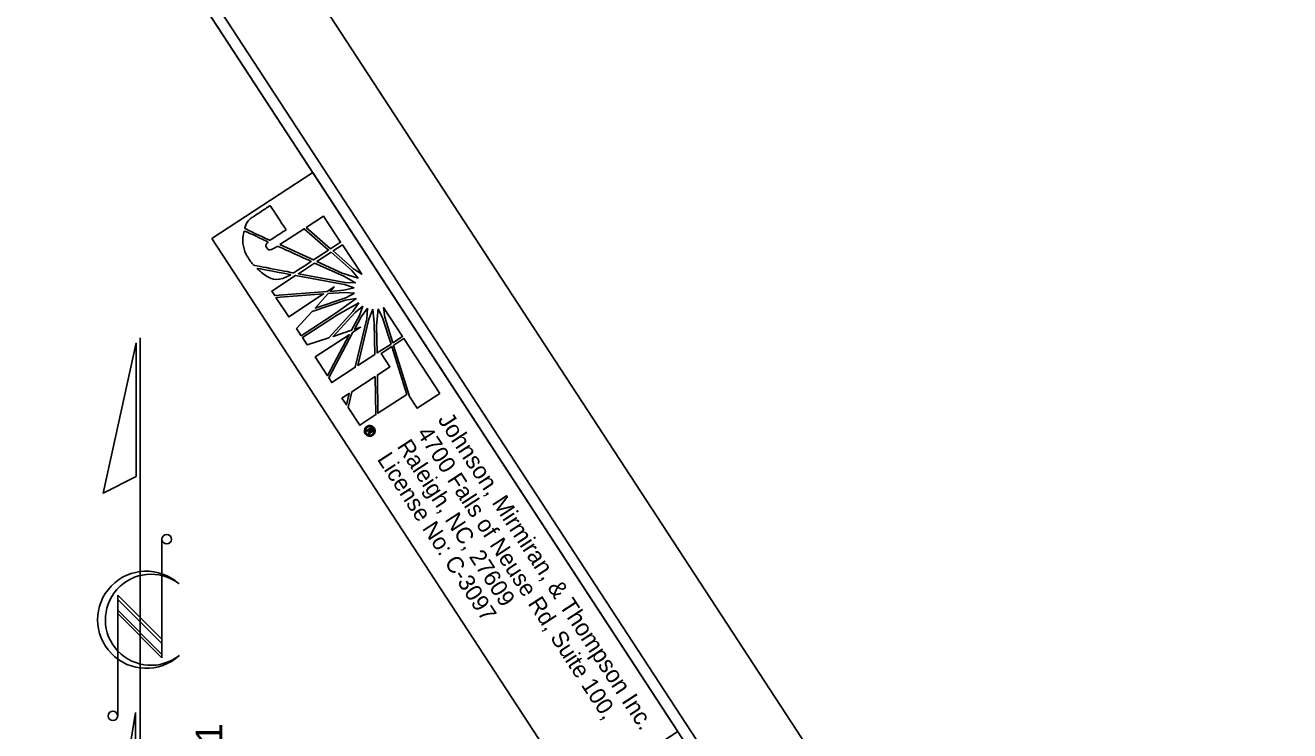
# Model space of a CAD drawing. Extents: x 1639622 to 2864602, y 842655 to 973236.
# Drawn here: x 1641174.9 to 1641458.9, y 843422.9 to 843581.5 of the extents above; entities that cross this region are included whole.
import ezdxf

# ---------------------------------------------------------------- set-up
doc = ezdxf.new("R2010")
doc.units = 0
for name, color, linetype in [('Prop Dimension Text', 7, 'Continuous'), ('Sheet North Arrow CELL', 7, 'Continuous'), ('Sheet Plan CELL', 7, 'Continuous'), ('Sheet Plot Border Inside CELL', 7, 'Continuous'), ('Sheet Plot Border Outside CELL', 7, 'Continuous')]:
    doc.layers.add(name, color=color, linetype=linetype)

msp = doc.modelspace()

# ---------------------------------------------------------------- linework, layer by layer
at = {"layer": 'Prop Dimension Text'}
for p, q in [((1641241.83, 843538.56), (1641237.94, 843536.01)), ((1641245.68, 843532.68), (1641241.83, 843538.56)), ((1641237.49, 843535.72), (1641232.01, 843532.14)), ((1641242.98, 843530.92), (1641237.49, 843535.72)), ((1641237.94, 843536.01), (1641243.41, 843531.2)), ((1641232.01, 843532.14), (1641239.58, 843528.69)), ((1641243.41, 843531.2), (1641245.68, 843532.68)), ((1641246.11, 843532.09), (1641244, 843530.71)), ((1641250.43, 843525.48), (1641246.11, 843532.09)), ((1641239.58, 843528.69), (1641242.98, 843530.92)), ((1641243.55, 843530.42), (1641240.37, 843528.34)), ((1641248.12, 843526.38), (1641243.55, 843530.42)), ((1641244, 843530.71), (1641248.58, 843526.68)), ((1641239.85, 843528), (1641236.19, 843525.6)), ((1641246.42, 843525.03), (1641239.85, 843528)), ((1641240.37, 843528.34), (1641246.04, 843525.75)), ((1641248.58, 843526.68), (1641250.43, 843525.48)), ((1641235.57, 843525.2), (1641230.23, 843521.71)), ((1641246.53, 843523.16), (1641235.57, 843525.2)), ((1641236.19, 843525.6), (1641246.69, 843523.62)), ((1641246.04, 843525.75), (1641249.61, 843524.61)), ((1641249.02, 843523.53), (1641246.42, 843525.03)), ((1641246.69, 843523.62), (1641249.02, 843523.53)), ((1641249.61, 843524.61), (1641248.12, 843526.38)), ((1641230.23, 843521.71), (1641230.87, 843520.74)), ((1641230.87, 843520.74), (1641242.68, 843521.62)), ((1641241.84, 843521.06), (1641231.16, 843520.29)), ((1641234.03, 843515.9), (1641241.84, 843521.06)), ((1641242.91, 843521.12), (1641240, 843517.87)), ((1641242.68, 843521.62), (1641244.24, 843522.63)), ((1641246.53, 843521.39), (1641242.91, 843521.12)), ((1641244.24, 843522.63), (1641243.36, 843521.64)), ((1641243.36, 843521.64), (1641246.4, 843521.88)), ((1641246.4, 843521.88), (1641248.75, 843522.39)), ((1641248.75, 843522.39), (1641246.53, 843523.16)), ((1641248.78, 843521.2), (1641246.53, 843521.39)), ((1641246.86, 843520.18), (1641248.78, 843521.2)), ((1641231.16, 843520.29), (1641234.03, 843515.9)), ((1641246.75, 843519.64), (1641239.31, 843517.14)), ((1641240, 843517.87), (1641246.86, 843520.18)), ((1641244.68, 843516.78), (1641249.15, 843520.06)), ((1641249.79, 843519.09), (1641244.96, 843516.36)), ((1641249.15, 843520.06), (1641246.75, 843519.64)), ((1641248.41, 843517.09), (1641249.79, 843519.09)), ((1641250.67, 843518.32), (1641248.91, 843516.9)), ((1641249.91, 843516.21), (1641250.67, 843518.32)), ((1641259.56, 843511.46), (1641255.33, 843517.99)), ((1641255.33, 843517.99), (1641255.63, 843515.84)), ((1641239.31, 843517.14), (1641235.8, 843513.26)), ((1641236.85, 843511.65), (1641244.68, 843516.78)), ((1641244.96, 843516.36), (1641237.12, 843511.24)), ((1641243.07, 843511.18), (1641248.41, 843517.09)), ((1641248.91, 843516.9), (1641243.97, 843511.5)), ((1641248.16, 843512.89), (1641249.91, 843516.21)), ((1641250.32, 843515.88), (1641248.81, 843513.09)), ((1641248.96, 843504.58), (1641251.55, 843515.48)), ((1641252.01, 843515.41), (1641249.57, 843504.98)), ((1641251.73, 843517.83), (1641250.32, 843515.88)), ((1641251.55, 843515.48), (1641251.73, 843517.83)), ((1641252.89, 843517.6), (1641252.01, 843515.41)), ((1641253.24, 843514.59), (1641252.89, 843517.6)), ((1641254.14, 843517.69), (1641253.73, 843513.91)), ((1641255.09, 843515.72), (1641254.14, 843517.69)), ((1641257, 843509.78), (1641255.09, 843515.72)), ((1641255.63, 843515.84), (1641257.44, 843510.07)), ((1641235.8, 843513.26), (1641236.85, 843511.65)), ((1641248.45, 843512.43), (1641243.01, 843502.17)), ((1641243.97, 843511.5), (1641248.16, 843512.89)), ((1641250.17, 843513.55), (1641248.45, 843512.43)), ((1641248.81, 843513.09), (1641250.17, 843513.55)), ((1641253.34, 843507.44), (1641253.24, 843514.59)), ((1641253.73, 843513.91), (1641253.86, 843507.79)), ((1641237.12, 843511.24), (1641238.19, 843509.61)), ((1641238.19, 843509.61), (1641243.07, 843511.18)), ((1641247.61, 843511.88), (1641239.97, 843506.88)), ((1641242.72, 843502.68), (1641247.61, 843511.88)), ((1641253.86, 843507.79), (1641257, 843509.78)), ((1641257.44, 843510.07), (1641259.56, 843511.46)), ((1641257.61, 843509.54), (1641257.55, 843509.49)), ((1641257.55, 843509.49), (1641261.18, 843497.98)), ((1641259.88, 843511.02), (1641257.61, 843509.54)), ((1641267.96, 843498.67), (1641259.88, 843511.02)), ((1641239.97, 843506.88), (1641242.72, 843502.68)), ((1641249.57, 843504.98), (1641253.34, 843507.44)), ((1641257.16, 843509.24), (1641254.79, 843507.69)), ((1641254.79, 843507.69), (1641256.77, 843504.67)), ((1641257.2, 843509.26), (1641257.16, 843509.24)), ((1641260.55, 843498.46), (1641257.2, 843509.26)), ((1641243.69, 843501.13), (1641248.96, 843504.58)), ((1641256.77, 843504.67), (1641253.94, 843502.83)), ((1641243.01, 843502.17), (1641243.69, 843501.13)), ((1641253.46, 843502.51), (1641248.2, 843499.08)), ((1641253.61, 843493.92), (1641253.46, 843502.51)), ((1641253.94, 843502.83), (1641254.07, 843494.22)), ((1641247.63, 843498.7), (1641245.98, 843497.62)), ((1641246.98, 843496.1), (1641247.63, 843498.7)), ((1641248.2, 843499.08), (1641247.36, 843495.52)), ((1641254.07, 843494.22), (1641260.55, 843498.46)), ((1641262.9, 843495.36), (1641267.96, 843498.67)), ((1641245.98, 843497.62), (1641246.98, 843496.1)), ((1641247.36, 843495.52), (1641249.96, 843491.53)), ((1641261.18, 843497.98), (1641262.9, 843495.36)), ((1641249.96, 843491.53), (1641253.61, 843493.92)), ((1641251.42, 843489.75), (1641251.22, 843489.62)), ((1641251.22, 843489.62), (1641251.42, 843489.75)), ((1641251.23, 843489.62), (1641251.22, 843489.62)), ((1641251.42, 843489.75), (1641251.43, 843489.75)), ((1641251.53, 843490.35), (1641252.43, 843490.94)), ((1641251.66, 843490.15), (1641251.53, 843490.35)), ((1641252.02, 843490.38), (1641251.66, 843490.15)), ((1641252.12, 843490.21), (1641252.02, 843490.38)), ((1641252.29, 843490.32), (1641252.12, 843490.21)), ((1641252.12, 843490.21), (1641252.29, 843490.32)), ((1641252.13, 843490.2), (1641252.12, 843490.21)), ((1641252.39, 843490.62), (1641252.18, 843490.48)), ((1641252.18, 843490.48), (1641252.29, 843490.32)), ((1641252.29, 843490.32), (1641252.29, 843490.31)), ((1641252.5, 843490.46), (1641252.39, 843490.62)), ((1641252.43, 843490.94), (1641252.67, 843490.57)), ((1641252.67, 843490.57), (1641252.5, 843490.46)), ((1641252.5, 843490.46), (1641252.67, 843490.57)), ((1641252.51, 843490.43), (1641252.5, 843490.46)), ((1641252.67, 843490.57), (1641252.71, 843490.51)), ((1641253.2, 843490.92), (1641253.01, 843490.79)), ((1641253.01, 843490.79), (1641253.2, 843490.92))]:
    msp.add_line(p, q, dxfattribs=at)
msp.add_lwpolyline([(1641216.75, 843533.53), (1641298.74, 843407.89), (1641321.42, 843422.68), (1641239.43, 843548.33)], close=True, dxfattribs=at)
for points in [[(1641237.94, 843536.01), (1641243.41, 843531.2), (1641245.68, 843532.68), (1641241.83, 843538.56), (1641237.94, 843536.01)], [(1641232.01, 843532.14), (1641239.58, 843528.69), (1641242.98, 843530.92), (1641237.49, 843535.72), (1641232.01, 843532.14)], [(1641248.58, 843526.68), (1641250.43, 843525.48), (1641246.11, 843532.09), (1641244, 843530.71), (1641248.58, 843526.68)], [(1641243.55, 843530.42), (1641240.37, 843528.34), (1641246.04, 843525.75), (1641249.61, 843524.61), (1641248.12, 843526.38), (1641243.55, 843530.42)], [(1641239.85, 843528), (1641236.19, 843525.6), (1641246.69, 843523.62), (1641249.02, 843523.53), (1641246.42, 843525.03), (1641239.85, 843528)], [(1641248.75, 843522.39), (1641246.53, 843523.16), (1641235.57, 843525.2), (1641230.23, 843521.71), (1641230.87, 843520.74), (1641242.68, 843521.62), (1641244.24, 843522.63), (1641243.36, 843521.64), (1641246.4, 843521.88), (1641248.75, 843522.39)], [(1641231.16, 843520.29), (1641234.03, 843515.9), (1641241.84, 843521.06), (1641231.16, 843520.29)], [(1641248.78, 843521.2), (1641246.53, 843521.39), (1641242.91, 843521.12), (1641240, 843517.87), (1641246.86, 843520.18), (1641248.78, 843521.2)], [(1641246.75, 843519.64), (1641239.31, 843517.14), (1641235.8, 843513.26), (1641236.85, 843511.65), (1641244.68, 843516.78), (1641249.15, 843520.06), (1641246.75, 843519.64)], [(1641249.79, 843519.09), (1641244.96, 843516.36), (1641237.12, 843511.24), (1641238.19, 843509.61), (1641243.07, 843511.18), (1641248.41, 843517.09), (1641249.79, 843519.09)], [(1641250.67, 843518.32), (1641248.91, 843516.9), (1641243.97, 843511.5), (1641248.16, 843512.89), (1641249.91, 843516.21), (1641250.67, 843518.32)], [(1641255.63, 843515.84), (1641257.44, 843510.07), (1641259.56, 843511.46), (1641255.33, 843517.99), (1641255.63, 843515.84)], [(1641251.73, 843517.83), (1641250.32, 843515.88), (1641248.81, 843513.09), (1641250.17, 843513.55), (1641248.45, 843512.43), (1641243.01, 843502.17), (1641243.69, 843501.13), (1641248.96, 843504.58), (1641251.55, 843515.48), (1641251.73, 843517.83)], [(1641252.89, 843517.6), (1641252.01, 843515.41), (1641249.57, 843504.98), (1641253.34, 843507.44), (1641253.24, 843514.59), (1641252.89, 843517.6)], [(1641254.14, 843517.69), (1641253.73, 843513.91), (1641253.86, 843507.79), (1641257, 843509.78), (1641255.09, 843515.72), (1641254.14, 843517.69)], [(1641239.97, 843506.88), (1641242.72, 843502.68), (1641247.61, 843511.88), (1641239.97, 843506.88)], [(1641267.96, 843498.67), (1641259.88, 843511.02), (1641257.61, 843509.54), (1641257.55, 843509.49), (1641261.18, 843497.98), (1641262.9, 843495.36), (1641267.96, 843498.67)], [(1641257.2, 843509.26), (1641257.16, 843509.24), (1641254.79, 843507.69), (1641256.77, 843504.67), (1641253.94, 843502.83), (1641254.07, 843494.22), (1641260.55, 843498.46), (1641257.2, 843509.26)], [(1641253.46, 843502.51), (1641248.2, 843499.08), (1641247.36, 843495.52), (1641249.96, 843491.53), (1641253.61, 843493.92), (1641253.46, 843502.51), (1641253.46, 843502.51)], [(1641245.98, 843497.62), (1641245.98, 843497.62), (1641246.98, 843496.1), (1641247.63, 843498.7), (1641245.98, 843497.62)], [(1641252.24, 843489.73), (1641252.19, 843489.7), (1641252.16, 843489.67), (1641252.13, 843489.65), (1641252.05, 843489.56), (1641251.93, 843489.75)]]:
    msp.add_lwpolyline(points, dxfattribs=at)
for points, degree in [([(1641233.43, 843535.47), (1641233.43, 843535.47), (1641229.87, 843540.91), (1641229.87, 843540.91), (1641229.87, 843540.91), (1641226.47, 843538.69), (1641226.47, 843538.69), (1641226.47, 843538.69), (1641226.11, 843538.45), (1641226.11, 843538.45), (1641225.04, 843537.75), (1641224.43, 843536.85), (1641224.13, 843535.77), (1641224.13, 843535.77), (1641229.76, 843533.07), (1641229.83, 843533.12), (1641229.83, 843533.12), (1641233.43, 843535.47), (1641233.43, 843535.47)], 3), ([(1641229.08, 843531.43), (1641228.86, 843531.77), (1641228.85, 843532.2), (1641229.42, 843532.75), (1641229.42, 843532.75), (1641224.05, 843535.27), (1641224.05, 843535.27), (1641223.54, 843533.07), (1641224.08, 843530.46), (1641225.23, 843528.71), (1641225.53, 843528.25), (1641225.79, 843527.93), (1641226.21, 843527.51), (1641226.21, 843527.51), (1641235.14, 843525.79), (1641235.14, 843525.79), (1641235.14, 843525.79), (1641239.09, 843528.38), (1641239.09, 843528.38), (1641239.09, 843528.38), (1641231.52, 843531.81), (1641231.52, 843531.81), (1641230.03, 843530.84), (1641229.4, 843530.94), (1641229.08, 843531.43)], 3), ([(1641229.08, 843531.43), (1641228.86, 843531.77), (1641228.85, 843532.2), (1641229.42, 843532.75), (1641229.42, 843532.75), (1641224.05, 843535.27), (1641224.05, 843535.27), (1641223.54, 843533.07), (1641224.08, 843530.46), (1641225.23, 843528.71), (1641225.53, 843528.25), (1641225.79, 843527.93), (1641226.21, 843527.51), (1641226.21, 843527.51), (1641235.14, 843525.79), (1641235.14, 843525.79), (1641235.14, 843525.79), (1641239.09, 843528.38), (1641239.09, 843528.38), (1641239.09, 843528.38), (1641231.52, 843531.81), (1641231.52, 843531.81), (1641230.03, 843530.84), (1641229.4, 843530.94), (1641229.08, 843531.43)], 3), ([(1641234.52, 843525.38), (1641234.52, 843525.38), (1641226.8, 843526.87), (1641226.8, 843526.87), (1641228.82, 843524.99), (1641231.76, 843523.73), (1641234.52, 843525.38)], 3), ([(1641251.22, 843489.62), (1641251.05, 843489.89), (1641250.99, 843490.2), (1641251.06, 843490.52), (1641251.12, 843490.84), (1641251.29, 843491.09), (1641251.57, 843491.27), (1641251.85, 843491.45), (1641252.15, 843491.51), (1641252.46, 843491.43), (1641252.77, 843491.36), (1641253.02, 843491.19), (1641253.2, 843490.92)], 3), ([(1641252.88, 843489.27), (1641252.6, 843489.09), (1641252.3, 843489.03), (1641251.98, 843489.09), (1641251.66, 843489.17), (1641251.41, 843489.34), (1641251.23, 843489.62)], 3), ([(1641253.01, 843490.79), (1641252.87, 843491.01), (1641252.67, 843491.15), (1641252.42, 843491.21), (1641252.17, 843491.27), (1641251.92, 843491.22), (1641251.7, 843491.08), (1641251.48, 843490.93), (1641251.33, 843490.72), (1641251.28, 843490.47), (1641251.23, 843490.21), (1641251.28, 843489.97), (1641251.42, 843489.75)], 3), ([(1641251.43, 843489.75), (1641251.57, 843489.52), (1641251.77, 843489.38), (1641252.02, 843489.33), (1641252.28, 843489.28), (1641252.53, 843489.32), (1641252.75, 843489.47), (1641252.97, 843489.61), (1641253.11, 843489.82), (1641253.17, 843490.08), (1641253.21, 843490.33), (1641253.16, 843490.57), (1641253.01, 843490.79)], 3), ([(1641251.93, 843489.75), (1641251.96, 843489.8), (1641252, 843489.85), (1641252.06, 843489.89), (1641252.14, 843489.95), (1641252.19, 843489.99), (1641252.2, 843490.03)], 3), ([(1641252.2, 843490.03), (1641252.2, 843490.06), (1641252.18, 843490.12), (1641252.13, 843490.2)], 2), ([(1641252.4, 843489.97), (1641252.4, 843489.89), (1641252.35, 843489.81), (1641252.24, 843489.73)], 2), ([(1641252.29, 843490.31), (1641252.38, 843490.18), (1641252.46, 843490.14), (1641252.53, 843490.19), (1641252.6, 843490.23), (1641252.59, 843490.31), (1641252.51, 843490.43)], 3), ([(1641252.71, 843490.51), (1641252.86, 843490.28), (1641252.84, 843490.11), (1641252.66, 843489.99), (1641252.58, 843489.94), (1641252.49, 843489.93), (1641252.4, 843489.97)], 3), ([(1641253.2, 843490.92), (1641253.38, 843490.64), (1641253.44, 843490.34), (1641253.38, 843490.02), (1641253.33, 843489.71), (1641253.15, 843489.45), (1641252.88, 843489.27)], 3)]:
    msp.add_open_spline(points, degree=degree, dxfattribs=at)
at = {"layer": 'Sheet North Arrow CELL'}
for p, q in [((1641200.65, 843381.18), (1641200.65, 843511.18)), ((1641205.55, 843465.94), (1641205.55, 843439.26)), ((1641209.23, 843456), (1641209.37, 843455.9)), ((1641205.55, 843443.42), (1641195.61, 843453.36)), ((1641195.61, 843453.36), (1641195.61, 843426.24)), ((1641205.55, 843442.44), (1641195.61, 843452.38)), ((1641195.61, 843452.38), (1641195.61, 843449.94)), ((1641205.55, 843440), (1641195.61, 843449.94)), ((1641195.61, 843449.94), (1641205.55, 843440)), ((1641205.55, 843439.26), (1641195.61, 843449.2)), ((1641205.55, 843440), (1641205.55, 843442.44))]:
    msp.add_line(p, q, dxfattribs=at)
for points in [[(1641199.75, 843510.04), (1641192.33, 843476.28), (1641199.75, 843480.04)], [(1641199.59, 843426.98), (1641192.23, 843381.18), (1641199.59, 843386.98)]]:
    msp.add_lwpolyline(points, close=True, dxfattribs=at)
for centre in [(1641206.61, 843465.92), (1641194.55, 843426.2)]:
    msp.add_circle(centre, 1.06, dxfattribs=at)
for centre, radius, start, end in [((1641202.03, 843447.81), 10.92, 47.84, 312.3941), ((1641203.09, 843447.81), 10.24, 53.095, 308.6287)]:
    msp.add_arc(centre, radius, start, end, dxfattribs=at)
at = {"layer": 'Sheet Plan CELL'}
for points in [[(1641430.74, 843255.12), (1640611, 844511.36), (1639731.66, 843937.55), (1640551.38, 842681.33)], [(1639731.66, 843937.55), (1640610.97, 844511.36), (1641321.42, 843422.68), (1641195.75, 843340.66), (1641305.06, 843173.13), (1640551.38, 842681.33)]]:
    msp.add_lwpolyline(points, close=True, dxfattribs=at)
at = {"layer": 'Sheet Plot Border Inside CELL'}
msp.add_lwpolyline([(1639645.67, 844064.72), (1640556.11, 842669.51), (1641439.64, 843246.03), (1640529.21, 844641.26)], close=True, dxfattribs=at)
at = {"layer": 'Sheet Plot Border Outside CELL'}
msp.add_lwpolyline([(1639621.82, 844064.68), (1640541.82, 842654.79), (1641458.85, 843253.19), (1640538.85, 844663.07)], close=True, dxfattribs=at)
msp.add_lwpolyline([(1639621.82, 844064.68), (1640541.82, 842654.79), (1641458.85, 843253.19), (1640538.85, 844663.07)], close=True, dxfattribs=at)

# ---------------------------------------------------------------- texts
at = {"layer": 'Prop Dimension Text'}
for s, height, p in [('Johnson, Mirmiran, & Thompson Inc.', 3.8334, (1641267.39, 843492.79)), ('4700 Falls of Neuse Rd, Suite 100, ', 3.7239, (1641262.67, 843489.72)), ('Raleigh, NC, 27609', 3.7239, (1641258.22, 843486.81)), ('License No: C-3097', 3.7239, (1641253.76, 843483.9))]:
    msp.add_text(s, height=height, rotation=303.1259, dxfattribs=at).set_placement(p)
at = {"layer": 'Sheet North Arrow CELL'}
msp.add_text('NA 2011', height=6, rotation=90, dxfattribs=at).set_placement((1641219.09, 843393.29))

doc.saveas('drawing.dxf')
